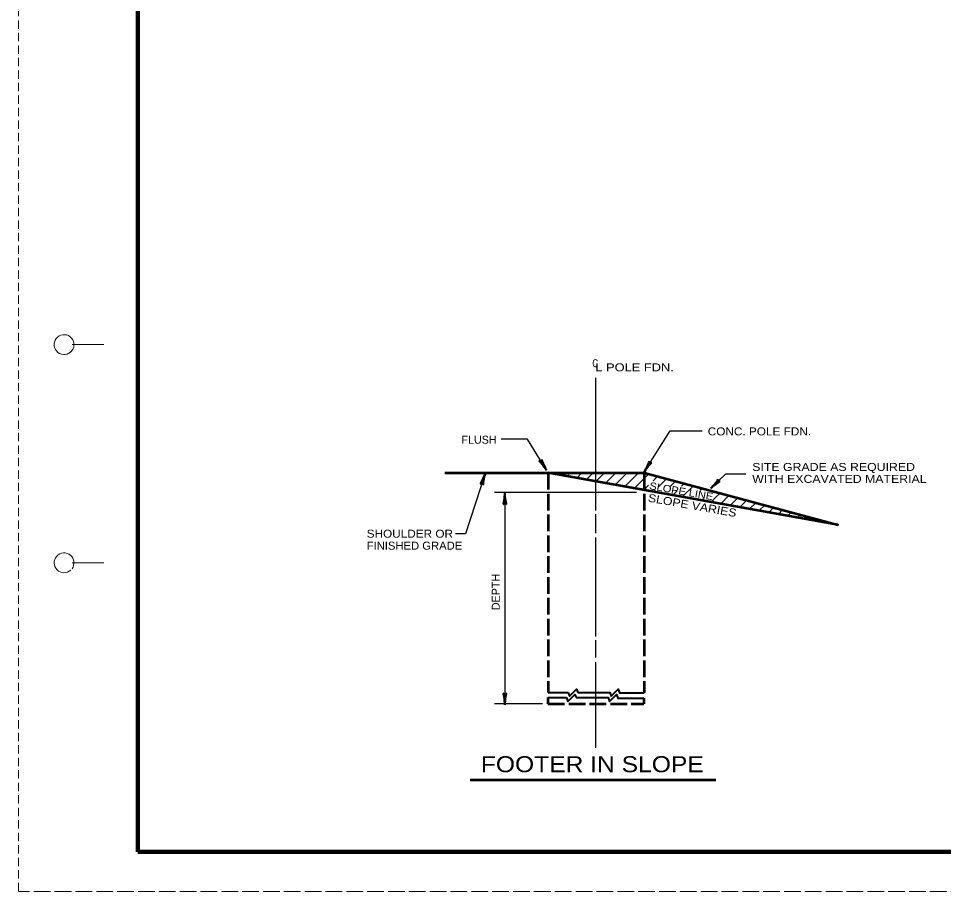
# Model space of a CAD drawing. Extents: x -1 to 679, y 0 to 440.
# Drawn here: x -1 to 232, y 0.3 to 220.3 of the extents above; entities that cross this region are included whole.
import ezdxf
from ezdxf.enums import TextEntityAlignment as Align

# ---------------------------------------------------------------- set-up
doc = ezdxf.new("R2010")
doc.units = 0
doc.header["$LTSCALE"] = 0.7
doc.linetypes.add('LONG_DASHED', pattern=[7.5, 6, -1.5])
doc.linetypes.add('MEDIUM_DASHED', pattern=[4.5, 3, -1.5])
doc.layers.add('1', color=7, linetype='Continuous', lineweight=53)
doc.layers.add('61', color=7, linetype='Continuous', lineweight=35)

msp = doc.modelspace()

# ---------------------------------------------------------------- linework, layer by layer
at = {"layer": '1', "linetype": 'MEDIUM_DASHED', "lineweight": 13}
msp.add_line((-0.9465, 440.3012), (-1.0065, 0.2612), dxfattribs=at)
at = {"layer": '1', "lineweight": 25}
for p, q in [((144.4668, 96.2911), (144.4668, 129.7311)), ((116.5868, 105.6111), (111.5868, 90.4111)), ((118.9068, 100.9311), (154.7068, 100.9311)), ((121.5068, 100.7511), (121.5068, 47.3511)), ((144.4668, 90.5911), (144.4668, 95.3511)), ((111.5868, 90.4111), (109.0668, 90.4311)), ((144.4668, 64.5511), (144.4668, 89.4511)), ((144.4668, 59.2311), (144.4668, 63.6111)), ((144.4668, 36.4311), (144.4668, 58.0911)), ((131.0068, 47.5511), (118.9068, 47.5511))]:
    msp.add_line(p, q, dxfattribs=at)
at = {"layer": '1'}
for p, q in [((106.3868, 105.7511), (156.7068, 105.7511)), ((112.7668, 28.3911), (174.6268, 28.3911))]:
    msp.add_line(p, q, dxfattribs=at)
at = {"layer": '1', "linetype": 'LONG_DASHED'}
for p, q in [((132.3868, 105.7511), (132.3868, 50.4111)), ((156.5668, 105.7511), (156.5668, 50.2911)), ((132.3668, 49.1311), (132.3668, 47.5711)), ((156.5468, 49.0111), (156.5468, 47.5711)), ((132.3668, 47.5711), (156.5468, 47.5711))]:
    msp.add_line(p, q, dxfattribs=at)
at = {"layer": '1', "lineweight": 35}
for p, q in [((137.1868, 104.8911), (138.0468, 105.7511)), ((139.6068, 104.4511), (140.9068, 105.7511)), ((142.0268, 104.0111), (143.7468, 105.7511)), ((144.4468, 103.5911), (146.6068, 105.7511)), ((146.8668, 103.1511), (149.4468, 105.7511)), ((149.2868, 102.7311), (152.3068, 105.7511)), ((151.7068, 102.2911), (155.1468, 105.7511)), ((154.1268, 101.8511), (157.7268, 105.4711)), ((158.8868, 103.7711), (159.9868, 104.8711)), ((156.5468, 101.4311), (157.7268, 102.6311)), ((160.1268, 102.1511), (162.2268, 104.2711)), ((163.1668, 102.3511), (164.4668, 103.6711)), ((166.0468, 102.3911), (166.7268, 103.0511)), ((158.9668, 100.9911), (159.3868, 101.4311)), ((161.3868, 100.5711), (161.5468, 100.7311)), ((163.7868, 100.1311), (164.8868, 101.2111)), ((166.2068, 99.6911), (168.9668, 102.4511)), ((170.7468, 101.3911), (171.2268, 101.8511)), ((173.2268, 101.0111), (173.4668, 101.2511)), ((174.5268, 99.4511), (175.7268, 100.6511)), ((168.6268, 99.2711), (168.8068, 99.4511)), ((171.0468, 98.8311), (171.4668, 99.2511)), ((173.4668, 98.4111), (174.7668, 99.6911)), ((175.8868, 97.9711), (177.9668, 100.0511)), ((178.3068, 97.5311), (180.2068, 99.4511)), ((180.7268, 97.1111), (182.4668, 98.8511)), ((183.1468, 96.6711), (184.7068, 98.2311)), ((185.5668, 96.2511), (186.9668, 97.6311)), ((187.9868, 95.8111), (189.2068, 97.0311)), ((190.4068, 95.3711), (191.4668, 96.4311)), ((192.8268, 94.9511), (193.7068, 95.8311)), ((195.2468, 94.5111), (195.9468, 95.2311)), ((197.6668, 94.0711), (198.2068, 94.6311))]:
    msp.add_line(p, q, dxfattribs=at)
at = {"layer": '1', "lineweight": 40}
for p, q in [((132.3668, 49.1311), (137.0268, 49.1311)), ((132.3868, 50.4111), (137.4668, 50.4111))]:
    msp.add_line(p, q, dxfattribs=at)
at = {"layer": '1', "lineweight": 25}
for points in [[(131.9668, 106.4511), (127.2068, 114.2311), (120.5668, 114.2311)], [(156.6668, 106.0711), (163.1268, 116.3311), (171.1868, 116.3311)], [(173.3868, 101.8911), (177.1868, 105.4911), (182.2268, 105.4911)]]:
    msp.add_lwpolyline(points, dxfattribs=at)
at = {"layer": '1'}
msp.add_lwpolyline([(156.7068, 105.7511), (205.3868, 92.6911), (132.3868, 105.7511)], dxfattribs=at)
at = {"layer": '1', "lineweight": 40}
for points in [[(137.0268, 49.1311), (137.3868, 48.1711), (139.1668, 49.9511), (139.4668, 49.1311)], [(137.4668, 50.4111), (137.8068, 49.4511), (139.5868, 51.2311), (139.8868, 50.4111)], [(139.4668, 49.1311), (147.5268, 49.1311), (147.8668, 48.1711), (149.6468, 49.9511), (150.0068, 49.0111), (156.5468, 49.0111)], [(139.8868, 50.4111), (147.9468, 50.4111), (148.3068, 49.4511), (150.0868, 51.2311), (150.4268, 50.2911), (156.5668, 50.2911)]]:
    msp.add_lwpolyline(points, dxfattribs=at)
for centre, major_axis, ratio, start_param, end_param in [((131.1564, 107.2452), (1.0715, -1.4549), 0.122415, 0.89635335, 3.14159265), ((131.1564, 107.2452), (1.0715, -1.4549), 0.122415, 0.89635335, 3.14159265), ((131.5609, 107.5265), (-0.7706, 1.6038), 0.07063, 6.28230741, 8.55970261), ((131.5609, 107.5265), (-0.7706, 1.6038), 0.07063, 6.28230741, 8.55970261), ((157.0172, 107.1503), (-0.8259, -1.6071), 0.122415, 0.89635335, 3.14159265), ((157.4491, 106.9132), (1.0932, 1.4039), 0.07063, 6.28230741, 8.55970261), ((116.0315, 104.6047), (-0.7211, -1.6266), 0.07063, 6.28230741, 8.55970261), ((116.5079, 104.4792), (0.4126, 1.7591), 0.122415, 0.89635335, 3.14159265), ((173.9924, 102.8506), (-1.1966, -1.3539), 0.122415, 0.89635335, 3.14159265), ((174.3526, 102.5144), (-1.4055, -1.0911), 0.07063, 3.14071475, 5.41810995), ((121.2935, 99.6216), (-0.1771, -1.7705), 0.07063, 6.28230741, 8.55970261), ((121.7853, 99.6512), (-0.1574, 1.8), 0.122415, 0.89635335, 3.14159265), ((121.2283, 48.451), (0.1574, -1.8), 0.122415, 0.89635335, 3.14159265), ((121.7201, 48.4805), (0.1771, 1.7705), 0.07063, 6.28230741, 8.55970261)]:
    msp.add_ellipse(centre, major_axis=major_axis, ratio=ratio, start_param=start_param, end_param=end_param, dxfattribs=at)
at = {"layer": '61', "lineweight": 13}
for p, q in [((12.4735, 138.1212), (20.4735, 138.1212)), ((12.4935, 83.1012), (20.4735, 83.1012))]:
    msp.add_line(p, q, dxfattribs=at)
at = {"layer": '61', "lineweight": 158}
msp.add_line((668.1135, 10.2612), (29.0535, 10.2812), dxfattribs=at)
at = {"layer": '61', "linetype": 'LONG_DASHED', "lineweight": 13}
msp.add_line((679.0535, 0.2812), (-1.0065, 0.2612), dxfattribs=at)
at = {"layer": '61', "lineweight": 158}
msp.add_lwpolyline([(668.0935, 430.3012), (29.0535, 430.3012), (29.0535, 10.2812)], dxfattribs=at)
at = {"layer": '61', "lineweight": 13}
for centre, start, end in [((10.4713, 138.1025), 322.67175, 321.71615), ((10.4713, 83.1025), 323.13009, 312.31439)]:
    msp.add_arc(centre, 2.5, start, end, dxfattribs=at)

# ---------------------------------------------------------------- texts
at = {"layer": '1'}
for s, width, p in [('C', 0.75, (143.5468, 132.3911)), ('L POLE FDN.', 1.2, (144.3068, 131.3511)), ('CONC. POLE FDN.', 1.1, (172.6268, 115.2111)), ('SITE GRADE AS REQUIRED', 1.15, (183.8268, 106.2511)), ('WITH EXCAVATED MATERIAL', 1.15, (183.8268, 103.2351)), ('SHOULDER OR', 1.1, (86.7068, 89.4311)), ('FINISHED GRADE', 1.05, (86.7068, 86.4111))]:
    msp.add_text(s, height=2.016, dxfattribs=dict(at, width=width)).set_placement(p)
msp.add_text('FLUSH', height=2.016, dxfattribs=at).set_placement((119.4329, 113.1111), align=Align.RIGHT)
at = {"layer": '1', "width": 1.15}
for s, height, p in [('SLOPE LINE', 1.814, (165.8157, 100.2695)), ('SLOPE VARIES', 2.016, (168.5636, 96.5826))]:
    msp.add_text(s, height=height, rotation=350, dxfattribs=at).set_placement(p, align=Align.CENTER)
at = {"layer": '1'}
msp.add_text('DEPTH', height=2.016, rotation=90, dxfattribs=at).set_placement((120.2268, 75.7396), align=Align.CENTER)
at = {"layer": '1', "width": 1.15}
msp.add_text('FOOTER IN SLOPE', height=4.032, dxfattribs=at).set_placement((143.5396, 30.3311), align=Align.CENTER)

doc.saveas('drawing.dxf')
